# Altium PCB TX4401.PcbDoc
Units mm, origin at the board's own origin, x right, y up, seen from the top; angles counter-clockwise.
Board outline 46 x 29.5 mm, 2 copper layers (Top Layer, Bottom Layer); 13 components, 13 nets, 38 pads, 35 vias.
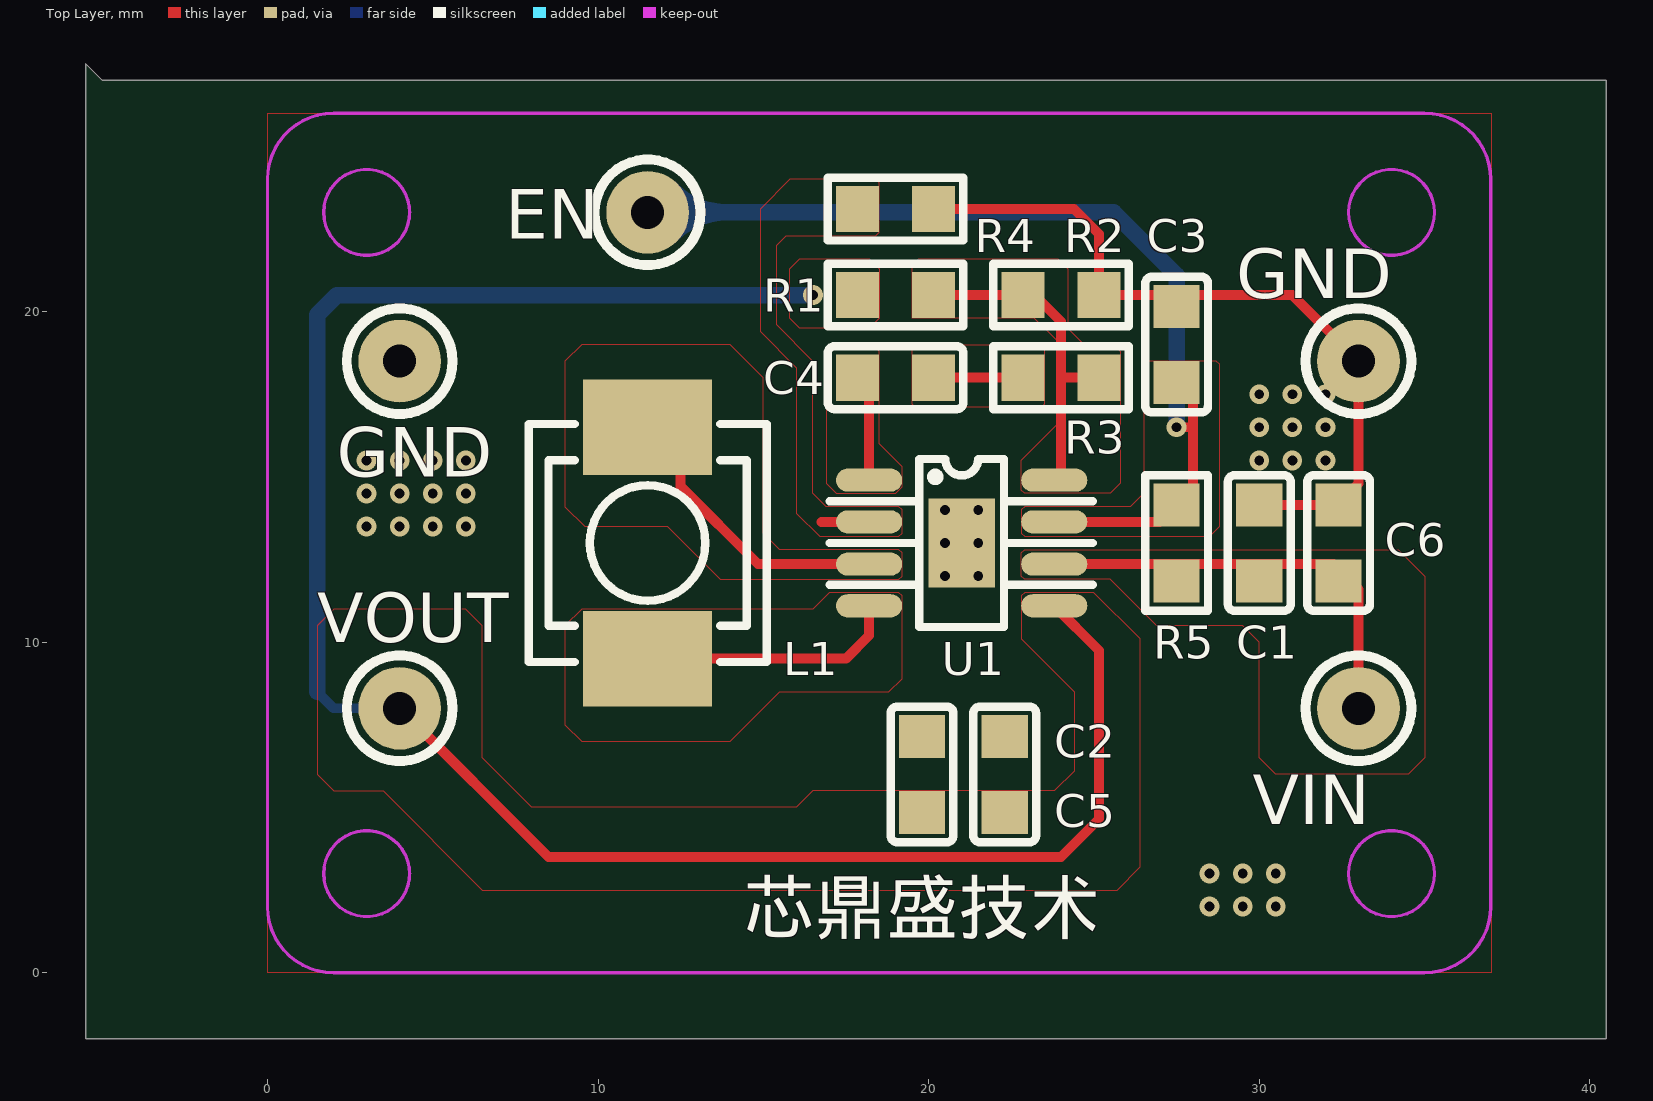
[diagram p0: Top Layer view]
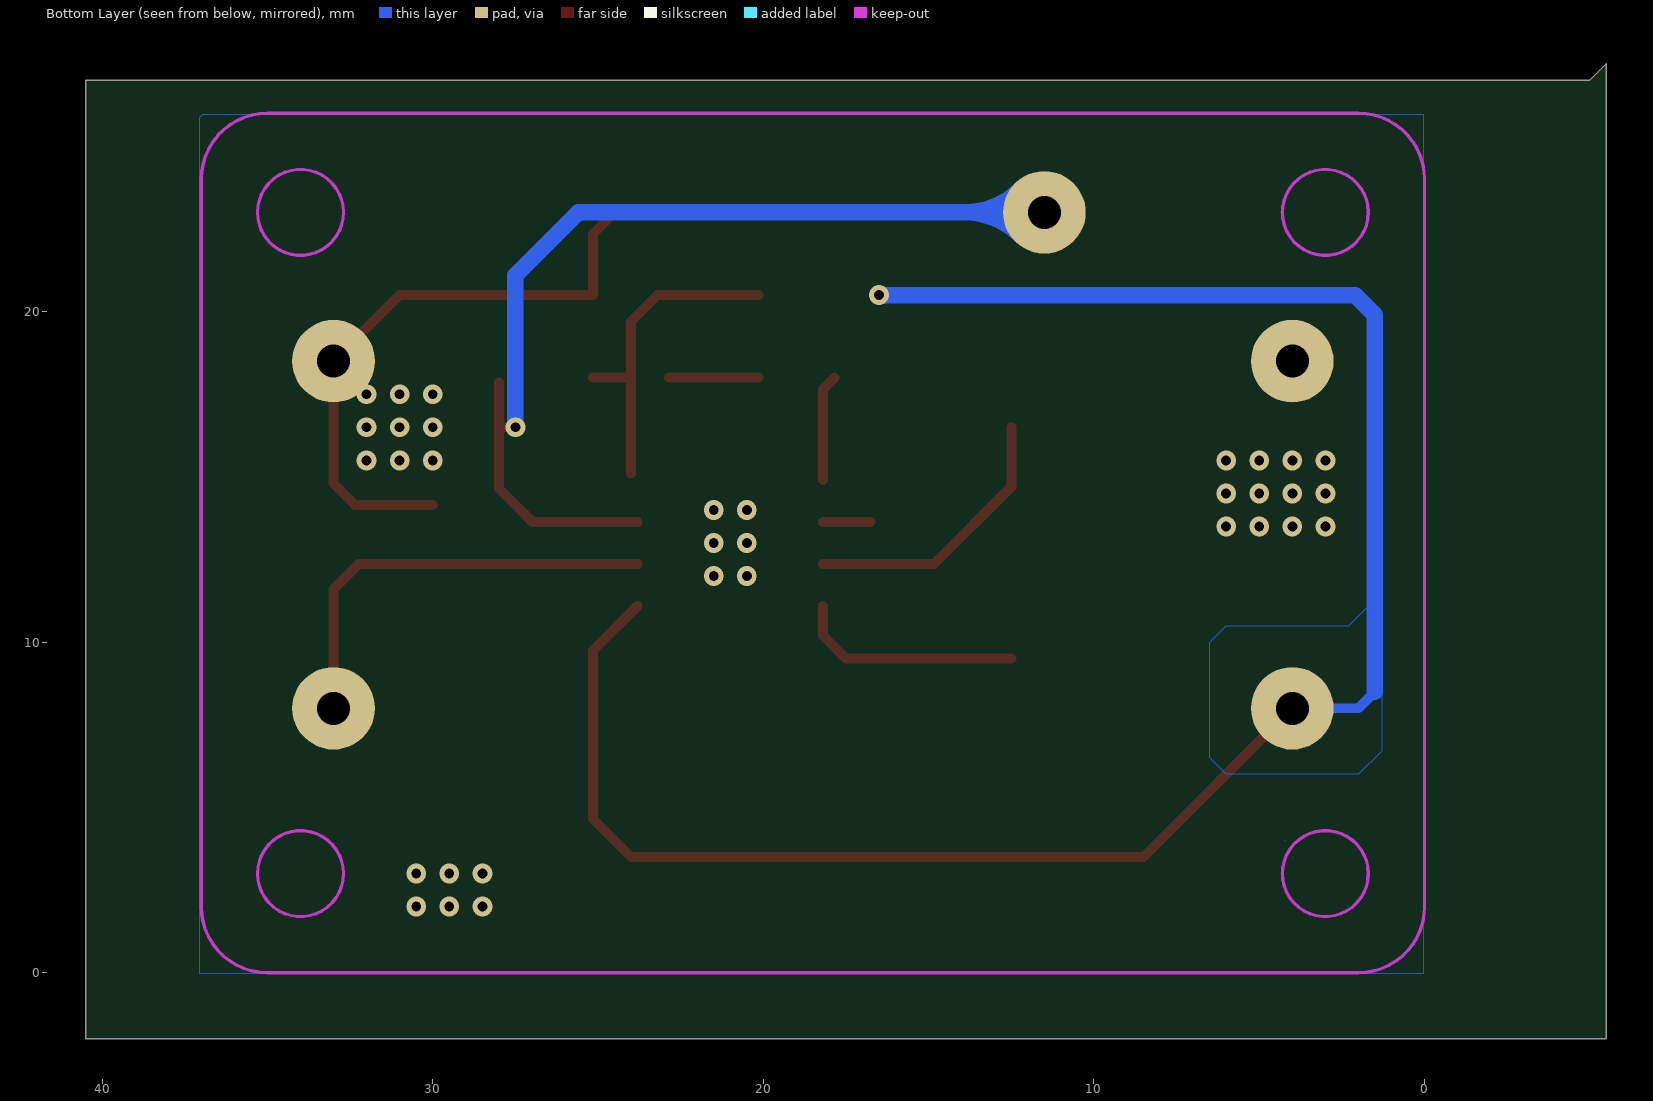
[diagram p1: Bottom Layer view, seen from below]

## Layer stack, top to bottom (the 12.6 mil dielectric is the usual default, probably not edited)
Top Layer: signal copper 0.0356
Dielectric: dielectric 0.32, FR-4, Dk 4.8
Bottom Layer: signal copper 0.0356

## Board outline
-5.5,-2 -5.5,27.5 -5,27 40.5,27 40.5,-2

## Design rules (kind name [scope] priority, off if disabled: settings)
Clearance [All] p0: scope1count=1 scope1_0_kind=Board scope1_0_value=Board scope2count=1 scope2_0_kind=Board scope2_0_value=Board commentlength=0 gap=0.3
Clearance [All] p1: gap=0.3
ComponentClearance [All] p0: scope1count=1 scope1_0_kind=Board scope1_0_value=Board scope2count=1 scope2_0_kind=Board scope2_0_value=Board commentlength=0 gap=0.254 collisioncheckmode=3
DiffPairsRouting [All] p0: scope1count=1 scope1_0_kind=Board scope1_0_value=Board scope2count=1 scope2_0_kind=Board scope2_0_value=Board commentlength=0
FanoutControl Fanout_BGA [All] p0 off: scope1count=1 scope1_0_kind=Board scope1_0_value=Board scope2count=1 scope2_0_kind=Board scope2_0_value=Board commentlength=69 // Protel DXP Scope 1 Expression Was: IsBGA   Fanout_BGA (Default Rule)
FanoutControl Fanout_LCC [All] p0 off: scope1count=1 scope1_0_kind=Board scope1_0_value=Board scope2count=1 scope2_0_kind=Board scope2_0_value=Board commentlength=69 // Protel DXP Scope 1 Expression Was: IsLCC   Fanout_LCC (Default Rule)
FanoutControl Fanout_SOIC [All] p0 off: scope1count=1 scope1_0_kind=Board scope1_0_value=Board scope2count=1 scope2_0_kind=Board scope2_0_value=Board commentlength=71 // Protel DXP Scope 1 Expression Was: IsSOIC   Fanout_SOIC (Default Rule)
FanoutControl Fanout_Small [All] p0 off: scope1count=1 scope1_0_kind=Board scope1_0_value=Board scope2count=1 scope2_0_kind=Board scope2_0_value=Board commentlength=84 // Protel DXP Scope 1 Expression Was: (CompPinCount < 5)   Fanout_Small (Default Rule)
FanoutControl Fanout_Default [All] p0: scope1count=1 scope1_0_kind=Board scope1_0_value=Board scope2count=1 scope2_0_kind=Board scope2_0_value=Board commentlength=30 // Fanout_Default (Default Rule)
Height [All] p0: scope1count=1 scope1_0_kind=Board scope1_0_value=Board scope2count=1 scope2_0_kind=Board scope2_0_value=Board commentlength=0
HoleSize [All] p0: scope1count=1 scope1_0_kind=Board scope1_0_value=Board scope2count=1 scope2_0_kind=Board scope2_0_value=Board commentlength=0 absolutevalues=TRUE maxlimit=2.54 minlimit=0.025 maxpercent=80.000 minpercent=20.000
HoleToHoleClearance [All] p0: scope1count=1 scope1_0_kind=Board scope1_0_value=Board scope2count=1 scope2_0_kind=Board scope2_0_value=Board commentlength=0
LayerPairs [All] p0: scope1count=1 scope1_0_kind=Board scope1_0_value=Board scope2count=1 scope2_0_kind=Board scope2_0_value=Board commentlength=0 enforce=TRUE
MinimumSolderMaskSliver [All] p0: scope1count=1 scope1_0_kind=Board scope1_0_value=Board scope2count=1 scope2_0_kind=Board scope2_0_value=Board commentlength=0
NetAntennae [All] p0: scope1count=1 scope1_0_kind=Board scope1_0_value=Board scope2count=1 scope2_0_kind=Board scope2_0_value=Board commentlength=0
PasteMaskExpansion [All] p0: scope1count=1 scope1_0_kind=Board scope1_0_value=Board scope2count=1 scope2_0_kind=Board scope2_0_value=Board commentlength=0 expansion=0
PlaneClearance [All] p0: scope1count=1 scope1_0_kind=Board scope1_0_value=Board scope2count=1 scope2_0_kind=Board scope2_0_value=Board commentlength=0 clearance=0.3
PlaneClearance [All] p1: clearance=0.3
PlaneConnect [All] p0: scope1count=1 scope1_0_kind=Board scope1_0_value=Board scope2count=1 scope2_0_kind=Board scope2_0_value=Board commentlength=0 planeconnectstyle=Direct reliefexpansion=0.508 reliefentries=4 reliefconductorwidth=0.254 reliefairgap=0.254
PlaneConnect [All] p1: planeconnectstyle=Direct reliefexpansion=0.508 reliefentries=4 reliefconductorwidth=0.254 reliefairgap=0.254
PolygonConnect [All] p0: scope1count=1 scope1_0_kind=Board scope1_0_value=Board scope2count=1 scope2_0_kind=Board scope2_0_value=Board commentlength=0 connectstyle=Direct reliefconductorwidth=0.254 reliefentries=4 polygonreliefangle="90 Angle"
PolygonConnect [All] p1: connectstyle=Direct reliefconductorwidth=0.254 reliefentries=4 polygonreliefangle="90 Angle"
RoutingCorners [All] p0: scope1count=1 scope1_0_kind=Board scope1_0_value=Board scope2count=1 scope2_0_kind=Board scope2_0_value=Board commentlength=0 cornerstyle=45-Degree minsetback=2.54 maxsetback=2.54
RoutingLayers [All] p0: scope1count=1 scope1_0_kind=Board scope1_0_value=Board scope2count=1 scope2_0_kind=Board scope2_0_value=Board commentlength=0 top layer=Automatic bottom layer=Automatic
RoutingPriority [All] p0: scope1count=1 scope1_0_kind=Board scope1_0_value=Board scope2count=1 scope2_0_kind=Board scope2_0_value=Board commentlength=0
RoutingTopology [All] p0: scope1count=1 scope1_0_kind=Board scope1_0_value=Board scope2count=1 scope2_0_kind=Board scope2_0_value=Board commentlength=0 topology=Shortest
RoutingVias [All] p0: scope1count=1 scope1_0_kind=Board scope1_0_value=Board scope2count=1 scope2_0_kind=Board scope2_0_value=Board commentlength=0 holewidth=0.711 width=1.27 viastyle="Through Hole" minholewidth=0.711 minwidth=1.27 maxholewidth=0.711 maxwidth=1.27
RoutingVias [All] p1: holewidth=0.711 width=1.27 viastyle="Through Hole" minholewidth=0.711 minwidth=1.27 maxholewidth=0.711 maxwidth=1.27
ShortCircuit [All] p0: scope1count=1 scope1_0_kind=Board scope1_0_value=Board scope2count=1 scope2_0_kind=Board scope2_0_value=Board commentlength=0 allowed=FALSE
SilkToSilkClearance [All] p0: scope1count=1 scope1_0_kind=Board scope1_0_value=Board scope2count=1 scope2_0_kind=Board scope2_0_value=Board commentlength=0
SilkscreenOverComponentPads [All] p0: scope1count=1 scope1_0_kind=Board scope1_0_value=Board scope2count=1 scope2_0_kind=Board scope2_0_value=Board commentlength=0
SilkscreenOverComponentPads [All] p1: minsilkscreentomaskgap=0.254
SolderMaskExpansion [All] p0: scope1count=1 scope1_0_kind=Board scope1_0_value=Board scope2count=1 scope2_0_kind=Board scope2_0_value=Board commentlength=0 expansion=0.3
SolderMaskExpansion [All] p1: expansion=0.3
TestPointUsage FabricationTestPointUsage [All] p0: scope1count=1 scope1_0_kind=Board scope1_0_value=Board scope2count=1 scope2_0_kind=Board scope2_0_value=Board commentlength=0 valid=0 allowmultiple=FALSE
TestPointUsage FabricationTestPointUsage [All] p1: valid=0 allowmultiple=FALSE
Testpoint FabricationTestpoint [All] p0: scope1count=1 scope1_0_kind=Board scope1_0_value=Board scope2count=1 scope2_0_kind=Board scope2_0_value=Board commentlength=0 side=3 testpointundercomponent=TRUE minsize=1.016 maxsize=2.54 preferedsize=1.524 minholesize=0 maxholesize=1.016 preferedholesize=0.813 testpointgrid=0.025 style=297 order=0123456789
Testpoint FabricationTestpoint [All] p1: side=3 testpointundercomponent=TRUE minsize=1.016 maxsize=2.54 preferedsize=1.524 minholesize=0 maxholesize=1.016 preferedholesize=0.813 testpointgrid=0.025 style=297 order=0123456789
UnRoutedNet [All] p0: scope1count=1 scope1_0_kind=Board scope1_0_value=Board scope2count=1 scope2_0_kind=Board scope2_0_value=Board commentlength=0
Width [All] p0: scope1count=1 scope1_0_kind=Board scope1_0_value=Board scope2count=1 scope2_0_kind=Board scope2_0_value=Board commentlength=0 maxlimit=0.3 minlimit=0.254 preferedwidth=0.254
Width [All] p1: maxlimit=0.3 minlimit=0.254 preferedwidth=0.254 toplayer_minwidth=0.3 toplayer_prefwidth=0.3 bottomlayer_minwidth=0.3 bottomlayer_prefwidth=0.3 minimp=50.000000 maximp=50.000000 favimp=50.000000
21 further rules are at their usual default settings.

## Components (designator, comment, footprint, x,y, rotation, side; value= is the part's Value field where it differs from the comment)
C1 "" C-0805 30,13 r90 top
C2 "" C-0805 22.3,6 r90 top
C3 "" C-0805 27.5,19 r90 top
C4 "" C-0805 19,18 r0 top
C5 "" C-0805 19.8,6 r270 top
C6 "" C-0805 32.4,13 r90 top
L1 "" "L7*7 A" 11.5,13 r270 top
R1 "" R-0805 19,20.5 r0 top
R2 "" R-0805 24,20.5 r0 top
R3 "" R-0805 24,18 r180 top
R4 "" R-0805 19,23.1 r180 top
R5 "" R-0805 27.5,13 r90 top
U1 "" SOP-8PP 21,13 r0 top

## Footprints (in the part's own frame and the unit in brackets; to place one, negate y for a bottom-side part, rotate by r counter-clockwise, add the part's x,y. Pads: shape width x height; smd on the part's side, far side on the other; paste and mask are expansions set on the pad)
C-0805 [mm]
  rect 1.3x1.4 smd: 1(-1.15,0) 2(1.15,0)
  silkscreen extent -2.05,-0.95 2.05,0.95
"L7*7 A" [mm]
  rect 2.9x3.9 smd: 1(-3.5,0) 2(3.5,0)
  silkscreen extent -3.6,-3.6 3.6,3.6
R-0805 [mm]
  rect 1.3x1.4 smd: 1(-1.15,0) 2(1.15,0)
  silkscreen extent -2.05,-0.95 2.05,0.95
SOP-8PP [mm]
  oval 2x0.7 smd: 1(-2.8,1.9) 2(-2.8,0.64) 3(-2.8,-0.64) 4(-2.8,-1.9) 5(2.8,-1.9) 6(2.8,-0.64) 7(2.8,0.64) 8(2.8,1.9)
  rect 2x2.7 smd: 9(0,0)
  silkscreen extent -4,-2.54 3.96,2.54

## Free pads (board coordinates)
  round 2.5 hole 1: 0(4,18.5) 1(4,8) 2(33,8) 3(33,18.5) 4(11.5,23)

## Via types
v1: diameter 0.6, hole 0.3, Top Layer to Bottom Layer, 35 vias

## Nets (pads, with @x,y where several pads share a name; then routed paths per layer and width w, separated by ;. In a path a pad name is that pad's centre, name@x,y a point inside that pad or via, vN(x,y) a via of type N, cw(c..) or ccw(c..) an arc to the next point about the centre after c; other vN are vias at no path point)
EN: C3.1 pad.4 R5.2 U1.7 | length 33.4
  Top Layer w0.3: U1.7 26.99,13.64 R5.2 28,14.65 C3.1@28,17.85 ; v1(27.5,16.5) 27.9,16.5
  Bottom Layer w0.5: pad.4 25.6,23 27.5,21.1 v1(27.5,16.5) ; pad.4@12.207,22.293 cw(c13.914,20.586) 13.914,23 cw(c13.914,25.414) pad.4@12.207,23.707
FB: R1.2 R2.1 R3.1 U1.8 | length 9.9
  Top Layer w0.3: R1.2 23.2,20.5 24,19.7 U1.8@24,15.1 ; 24,18 R3.1
GND: C1.2 C2.2 C3.2 C5.1 C6.2 pad.0 pad.3 R2.2 R4.1 U1.9 | length 22.8
  Top Layer w0.3: R4.1 24.4,23.1 25.15,22.35 R2.2 31,20.5 pad.3 33,14.8 32.35,14.15 C1.2
  other v1: 28.5,2 29.5,2 30.5,2 28.5,3 29.5,3 30.5,3 20.5,12 21.5,12 20.5,13 21.5,13 3,13.5 4,13.5 5,13.5 6,13.5 20.5,14 21.5,14 3,14.5 4,14.5 5,14.5 6,14.5 3,15.5 4,15.5 5,15.5 6,15.5 30,15.5 31,15.5 32,15.5 30,16.5 31,16.5 32,16.5 30,17.5 31,17.5 32,17.5
N1: 
N2: C4.2 R3.2 | length 2.7
  Top Layer w0.3: C4.2 R3.2
N3: 
N4: 
RT: R4.2 U1.2 | length 1.4
  Top Layer w0.3: 16.76,13.64 U1.2
SW1: L1.1 U1.3 | length 8.5
  Top Layer w0.3: L1.1@12.5,16.5 12.5,14.7 14.84,12.36 U1.3
SW2: L1.2 U1.4 | length 6.9
  Top Layer w0.3: L1.2@12.5,9.5 17.5,9.5 18.2,10.2 U1.4
VC: C4.1 U1.1 | length 3.2
  Top Layer w0.3: C4.1 18.2,17.65 U1.1
VIN: C1.1 C6.1 pad.2 R5.1 U1.6 | length 13.1
  Top Layer w0.3: U1.6 32.24,12.36 33,11.6 pad.2
VOUT: C2.1 C5.2 pad.1 R1.1 U1.5 | length 59.9
  Top Layer w0.3: pad.1 8.5,3.5 24,3.5 25.15,4.65 25.15,7 25.15,9.75 U1.5
  Bottom Layer w0.3: 1.5,8.5 2,8 pad.1
  Bottom Layer w0.5: 1.5,8.5 1.5,19.9 2.1,20.5 15.5,20.5 v1(16.5,20.5)

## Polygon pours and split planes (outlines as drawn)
N2 on Top Layer "Keep-Out Layer-No Net" (solid, pour order 53): 23,17.1 19.6,17.1 19.5,17.2 19.5,18.9 19.6,19 23.4,19 23.5,18.9 23.5,17.2 23.4,17.1
FB on Top Layer "Keep-Out Layer-No Net" (solid, pour order 51): 25.8,14.8 25.5,14.5 22.9,14.5 22.8,14.6 22.8,15.5 23.9,16.6 23.9,19.1 23.2,19.8 19.5,19.8 19.5,21.4 19.7,21.6 23.9,21.6 24.2,21.3 24.2,19.5 24.7,19 25.6,19 25.8,18.8
EN on Top Layer "Keep-Out Layer-No Net" (solid, pour order 49): 23,13.2 28.1,13.2 28.5,13.2 28.8,13.5 28.8,18.4 28.7,18.5 26.6,18.5 26.5,18.4 26.5,14.5 26.1,14.1 22.9,14.1 22.8,14 22.8,13.3 22.9,13.2
VIN on Top Layer "Keep-Out Layer-No Net" (solid, pour order 47): 23,12.8 34.2,12.8 35,12 35,6.5 34.5,6 30.5,6 30,6.5 30,10 29.5,10.5 26.9,10.5 25.5,11.9 22.9,11.9 22.8,12 22.8,12.7 22.9,12.8
SW2 on Top Layer "Keep-Out Layer-No Net" (solid, pour order 43): 19,11.5 17,11.5 16.5,11 9.5,11 9,10.5 9,7.5 9.5,7 14,7 15.5,8.5 16.8,8.5 18.8,8.5 19.2,8.9 19.2,11.4 19.1,11.5
GND on Top Layer "Keep-Out Layer-No Net" (solid, remove dead copper, pour order 24): 0.011,0 0.011,26 37.011,26 37.011,0
VOUT on Top Layer "Bottom Solder-No Net" (solid, remove dead copper, pour order 19): 16.1,19.5 15.8,19.8 15.8,21.3 16.1,21.6 18.2,21.6 18.5,21.3 18.5,19.8 18.2,19.5
VOUT on Top Layer "Bottom Solder-No Net" (solid, remove dead copper, pour order 21): 22.9,11.5 22.8,11.4 22.8,10.1 24.4,8.5 24.4,6.1 23.8,5.5 16.5,5.5 16,5 8,5 6.5,6.5 6.5,10.5 6,11 2,11 1.5,10.5 1.5,6 2,5.5 3.5,5.5 6.5,2.5 25.7,2.5 26.4,3.2 26.4,10.1 25,11.5
VC on Top Layer "Keep-Out Layer-No Net" (solid, pour order 45): 19.2,15.3 18.5,16 18.5,18.8 18.3,19 17.2,19 16.9,18.7 16.9,14.8 17.2,14.5 19,14.5 19.2,14.7
RT on Top Layer "Bottom Solder-No Net" (solid, remove dead copper, pour order 25): 16.9,14.1 16.5,14.5 16.5,18.5 15.4,19.6 15.4,22 15.7,22.3 18.4,22.3 18.5,22.4 18.5,23.9 18.4,24 15.8,24 14.9,23.1 14.9,19.4 16,18.3 16,13.9 16.7,13.2 19.1,13.2 19.2,13.3 19.2,14 19.1,14.1
SW1 on Top Layer "Keep-Out Layer-No Net" (solid, pour order 41): 15.5,12.8 15,13.3 15,18 14,19 9.5,19 9,18.5 9,14.1 9.6,13.5 12.1,13.5 13.7,11.9 19.1,11.9 19.2,12 19.2,12.7 19.1,12.8
GND on Bottom Layer "Keep-Out Layer-No Net" (solid, remove dead copper, pour order 26): 0.046,-0.028 37.046,-0.028 37.046,25.872 36.946,25.972 0.046,25.972
VOUT on Bottom Layer "Bottom Solder-No Net" (solid, remove dead copper, pour order 23): 5,10.5 2.3,10.5 1.3,11.5 1.3,6.7 2,6 6,6 6.5,6.5 6.5,10 6,10.5
FB on Top Paste "Keep-Out Layer-No Net" (solid): 23.8,14.9 24.7,14.9 23.8,15.8 22.9,14.9
VC on Top Paste "Keep-Out Layer-No Net" (solid): 18.2,14.9 17.3,14.9 18.2,15.8 19,15 19,14.9
SW2 on Top Paste "Keep-Out Layer-No Net" (solid): 18.2,11.1 17.3,11.1 18.2,10.2 19,11 19,11.1
VOUT on Top Paste "Keep-Out Layer-No Net" (solid): 23.8,11.1 24.8,11.1 23.8,10.1 22.9,11 22.9,11.1
GND on Bottom Paste "Keep-Out Layer-No Net" (solid): 25.7,9.5 18.2,9.5 17.7,10 17.7,15.5 18.2,16 26.2,16 26.7,15.5 26.7,10 26.2,9.5

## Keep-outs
Keep-Out Layer:
  circle w0.1: c3,3 r1.3
  circle w0.1: c3,23 r1.3
  circle w0.1: c34,23 r1.3
  circle w0.1: c34,3 r1.3
  lines w0.1: 0,2 ccw(c2,2) 2,0 35,0 ccw(c35,2) 37,2 37,24 ccw(c35,24) 35,26 2,26 ccw(c2,24) 0,24 0,2

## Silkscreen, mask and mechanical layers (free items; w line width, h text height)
Top Overlay:
  circle w0.3: c11.5,23 r1.6
  circle w0.3: c33,8 r1.6
  circle w0.3: c33,18.5 r1.6
  circle w0.3: c4,18.5 r1.6
  circle w0.3: c4,8 r1.6
  text "EN" at 7.2,22.2 h1.5
  text "GND" at 29.3,20.4 h1.5
  text "GND" at 2.1,15 h1.5
  text "VOUT" at 1.5,10 h1.5
  text "VIN" at 29.8,4.5 h1.5
  text "芯鼎盛技术" at 14.4,0.7 h2.7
